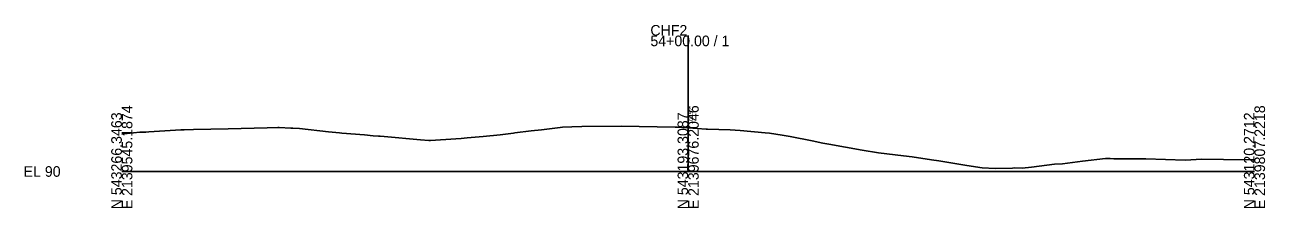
# Model space of a CAD drawing. Extents: x -12831 to 2303, y -10 to 39065.
# Drawn here: x 1974.3 to 2302.8, y 7990.3 to 8038.8 of the extents above; entities that cross this region are included whole.
import ezdxf

# ---------------------------------------------------------------- set-up
doc = ezdxf.new("R2010")
doc.units = 0
for name, color, linetype in [('RD_GPK_XS_Cell', 7, 'Continuous'), ('RD_XS_ExGround', 7, 'Continuous'), ('RD_XS_TX_Elev_EX', 7, 'Continuous')]:
    doc.layers.add(name, color=color, linetype=linetype)

msp = doc.modelspace()

# ---------------------------------------------------------------- linework, layer by layer
at = {"layer": 'RD_GPK_XS_Cell'}
for p, q in [((2150, 8000), (2150, 8035.91)), ((2000, 8000), (2150, 8000)), ((2150, 8000), (2300, 8000))]:
    msp.add_line(p, q, dxfattribs=at)
at = {"layer": 'RD_XS_ExGround'}
for p, q in [((2000, 8009.84), (2001.46, 8010.02)), ((2001.46, 8010.02), (2004.76, 8010.35)), ((2004.76, 8010.35), (2006.37, 8010.42)), ((2006.37, 8010.42), (2007.13, 8010.48)), ((2007.13, 8010.48), (2015.63, 8010.97)), ((2015.63, 8010.97), (2016.51, 8011.02)), ((2016.51, 8011.02), (2019.02, 8011.08)), ((2019.02, 8011.08), (2028.19, 8011.3)), ((2028.19, 8011.3), (2038.47, 8011.53)), ((2038.47, 8011.53), (2041.35, 8011.59)), ((2041.35, 8011.59), (2041.67, 8011.58)), ((2041.67, 8011.58), (2044.8, 8011.44)), ((2044.8, 8011.44), (2045.27, 8011.44)), ((2045.27, 8011.44), (2047.08, 8011.33)), ((2047.08, 8011.33), (2054.77, 8010.5)), ((2054.77, 8010.5), (2057.62, 8010.18)), ((2057.62, 8010.18), (2058.3, 8010.13)), ((2058.3, 8010.13), (2064.27, 8009.64)), ((2064.27, 8009.64), (2066.61, 8009.44)), ((2095.67, 8009.28), (2100.23, 8009.72)), ((2100.23, 8009.72), (2103.72, 8010.15)), ((2103.72, 8010.15), (2104.06, 8010.18)), ((2104.06, 8010.18), (2108.46, 8010.7)), ((2108.46, 8010.7), (2111.14, 8011.01)), ((2111.14, 8011.01), (2116.07, 8011.6)), ((2116.07, 8011.6), (2116.75, 8011.69)), ((2116.75, 8011.69), (2119.23, 8011.81)), ((2119.23, 8011.81), (2121.87, 8011.85)), ((2121.87, 8011.85), (2132.29, 8011.97)), ((2132.29, 8011.97), (2141.79, 8011.81)), ((2141.79, 8011.81), (2146.53, 8011.72)), ((2146.53, 8011.72), (2147.22, 8011.69)), ((2147.22, 8011.69), (2150, 8011.52)), ((2150, 8011.52), (2154.78, 8011.22)), ((2154.78, 8011.22), (2155.11, 8011.22)), ((2155.11, 8011.22), (2161.14, 8011.01)), ((2161.14, 8011.01), (2163.8, 8010.85)), ((2163.8, 8010.85), (2170.4, 8010.24)), ((2170.4, 8010.24), (2171.58, 8010.11)), ((2171.58, 8010.11), (2173.2, 8009.86)), ((2173.2, 8009.86), (2174.86, 8009.6)), ((2066.61, 8009.44), (2067.95, 8009.33)), ((2067.95, 8009.33), (2068.43, 8009.29)), ((2068.43, 8009.29), (2069.49, 8009.21)), ((2069.49, 8009.21), (2079.08, 8008.36)), ((2079.08, 8008.36), (2081.3, 8008.22)), ((2081.3, 8008.22), (2081.72, 8008.21)), ((2081.72, 8008.21), (2088.45, 8008.66)), ((2088.45, 8008.66), (2089.87, 8008.72)), ((2089.87, 8008.72), (2091.44, 8008.88)), ((2091.44, 8008.88), (2095.67, 8009.28)), ((2174.86, 8009.6), (2176.98, 8009.21)), ((2176.98, 8009.21), (2182.85, 8008.07)), ((2182.85, 8008.07), (2185.67, 8007.51)), ((2185.67, 8007.51), (2187.3, 8007.23)), ((2187.3, 8007.23), (2196.13, 8005.6)), ((2196.13, 8005.6), (2200.44, 8004.94)), ((2200.44, 8004.94), (2207.08, 8004.15)), ((2207.08, 8004.15), (2209.32, 8003.87)), ((2209.32, 8003.87), (2214.5, 8003.06)), ((2214.5, 8003.06), (2216.39, 8002.79)), ((2254.41, 8002.74), (2260.52, 8003.41)), ((2260.52, 8003.41), (2261.82, 8003.43)), ((2261.82, 8003.43), (2262.74, 8003.32)), ((2262.74, 8003.32), (2270.77, 8003.32)), ((2270.77, 8003.32), (2271.2, 8003.31)), ((2271.2, 8003.31), (2281.62, 8002.97)), ((2281.62, 8002.97), (2286.06, 8003.22)), ((2286.06, 8003.22), (2291.8, 8003.2)), ((2291.8, 8003.2), (2299.09, 8003.11)), ((2299.09, 8003.11), (2300, 8003.11)), ((2216.39, 8002.79), (2223.79, 8001.6)), ((2223.79, 8001.6), (2227.89, 8001)), ((2227.89, 8001), (2231.28, 8000.81)), ((2231.28, 8000.81), (2235.93, 8000.89)), ((2235.93, 8000.89), (2236.32, 8000.95)), ((2236.32, 8000.95), (2238.49, 8000.84)), ((2238.49, 8000.84), (2240.97, 8001.14)), ((2240.97, 8001.14), (2247.01, 8001.91)), ((2247.01, 8001.91), (2249.13, 8002.06)), ((2249.13, 8002.06), (2254.41, 8002.74))]:
    msp.add_line(p, q, dxfattribs=at)

# ---------------------------------------------------------------- texts
at = {"layer": 'RD_GPK_XS_Cell'}
for s, p in [('54+00.00 / 1', (2140, 8033.11)), ('CHF2', (2140, 8035.91)), ('EL 90', (1974, 7998.6))]:
    msp.add_text(s, height=2.8, dxfattribs=at).set_placement(p)
for s, p in [('E 2139545.1874', (2002.8, 7990)), ('E 2139676.2046', (2152.8, 7990)), ('E 2139807.2218', (2302.8, 7990)), ('N 543266.3463', (2000, 7990)), ('N 543193.3087', (2150, 7990)), ('N 543120.2712', (2300, 7990))]:
    msp.add_text(s, height=2.8, rotation=90, dxfattribs=at).set_placement(p)
at = {"layer": 'RD_XS_TX_Elev_EX'}
msp.add_text('101.52', height=1, rotation=90, dxfattribs=at).set_placement((2151.25, 8012.52))

doc.saveas('drawing.dxf')
